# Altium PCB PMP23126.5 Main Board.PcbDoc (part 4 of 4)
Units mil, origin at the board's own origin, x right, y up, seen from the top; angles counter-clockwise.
Board outline 7480.32 x 4667 mil, 6 copper layers (Top Layer, Signal Layer 1, Signal Layer 2, Signal Layer 3, Signal Layer 4, Bottom Layer), stack 65.8 mil thick; 166 components, 83 nets, 633 pads, 4418 vias.
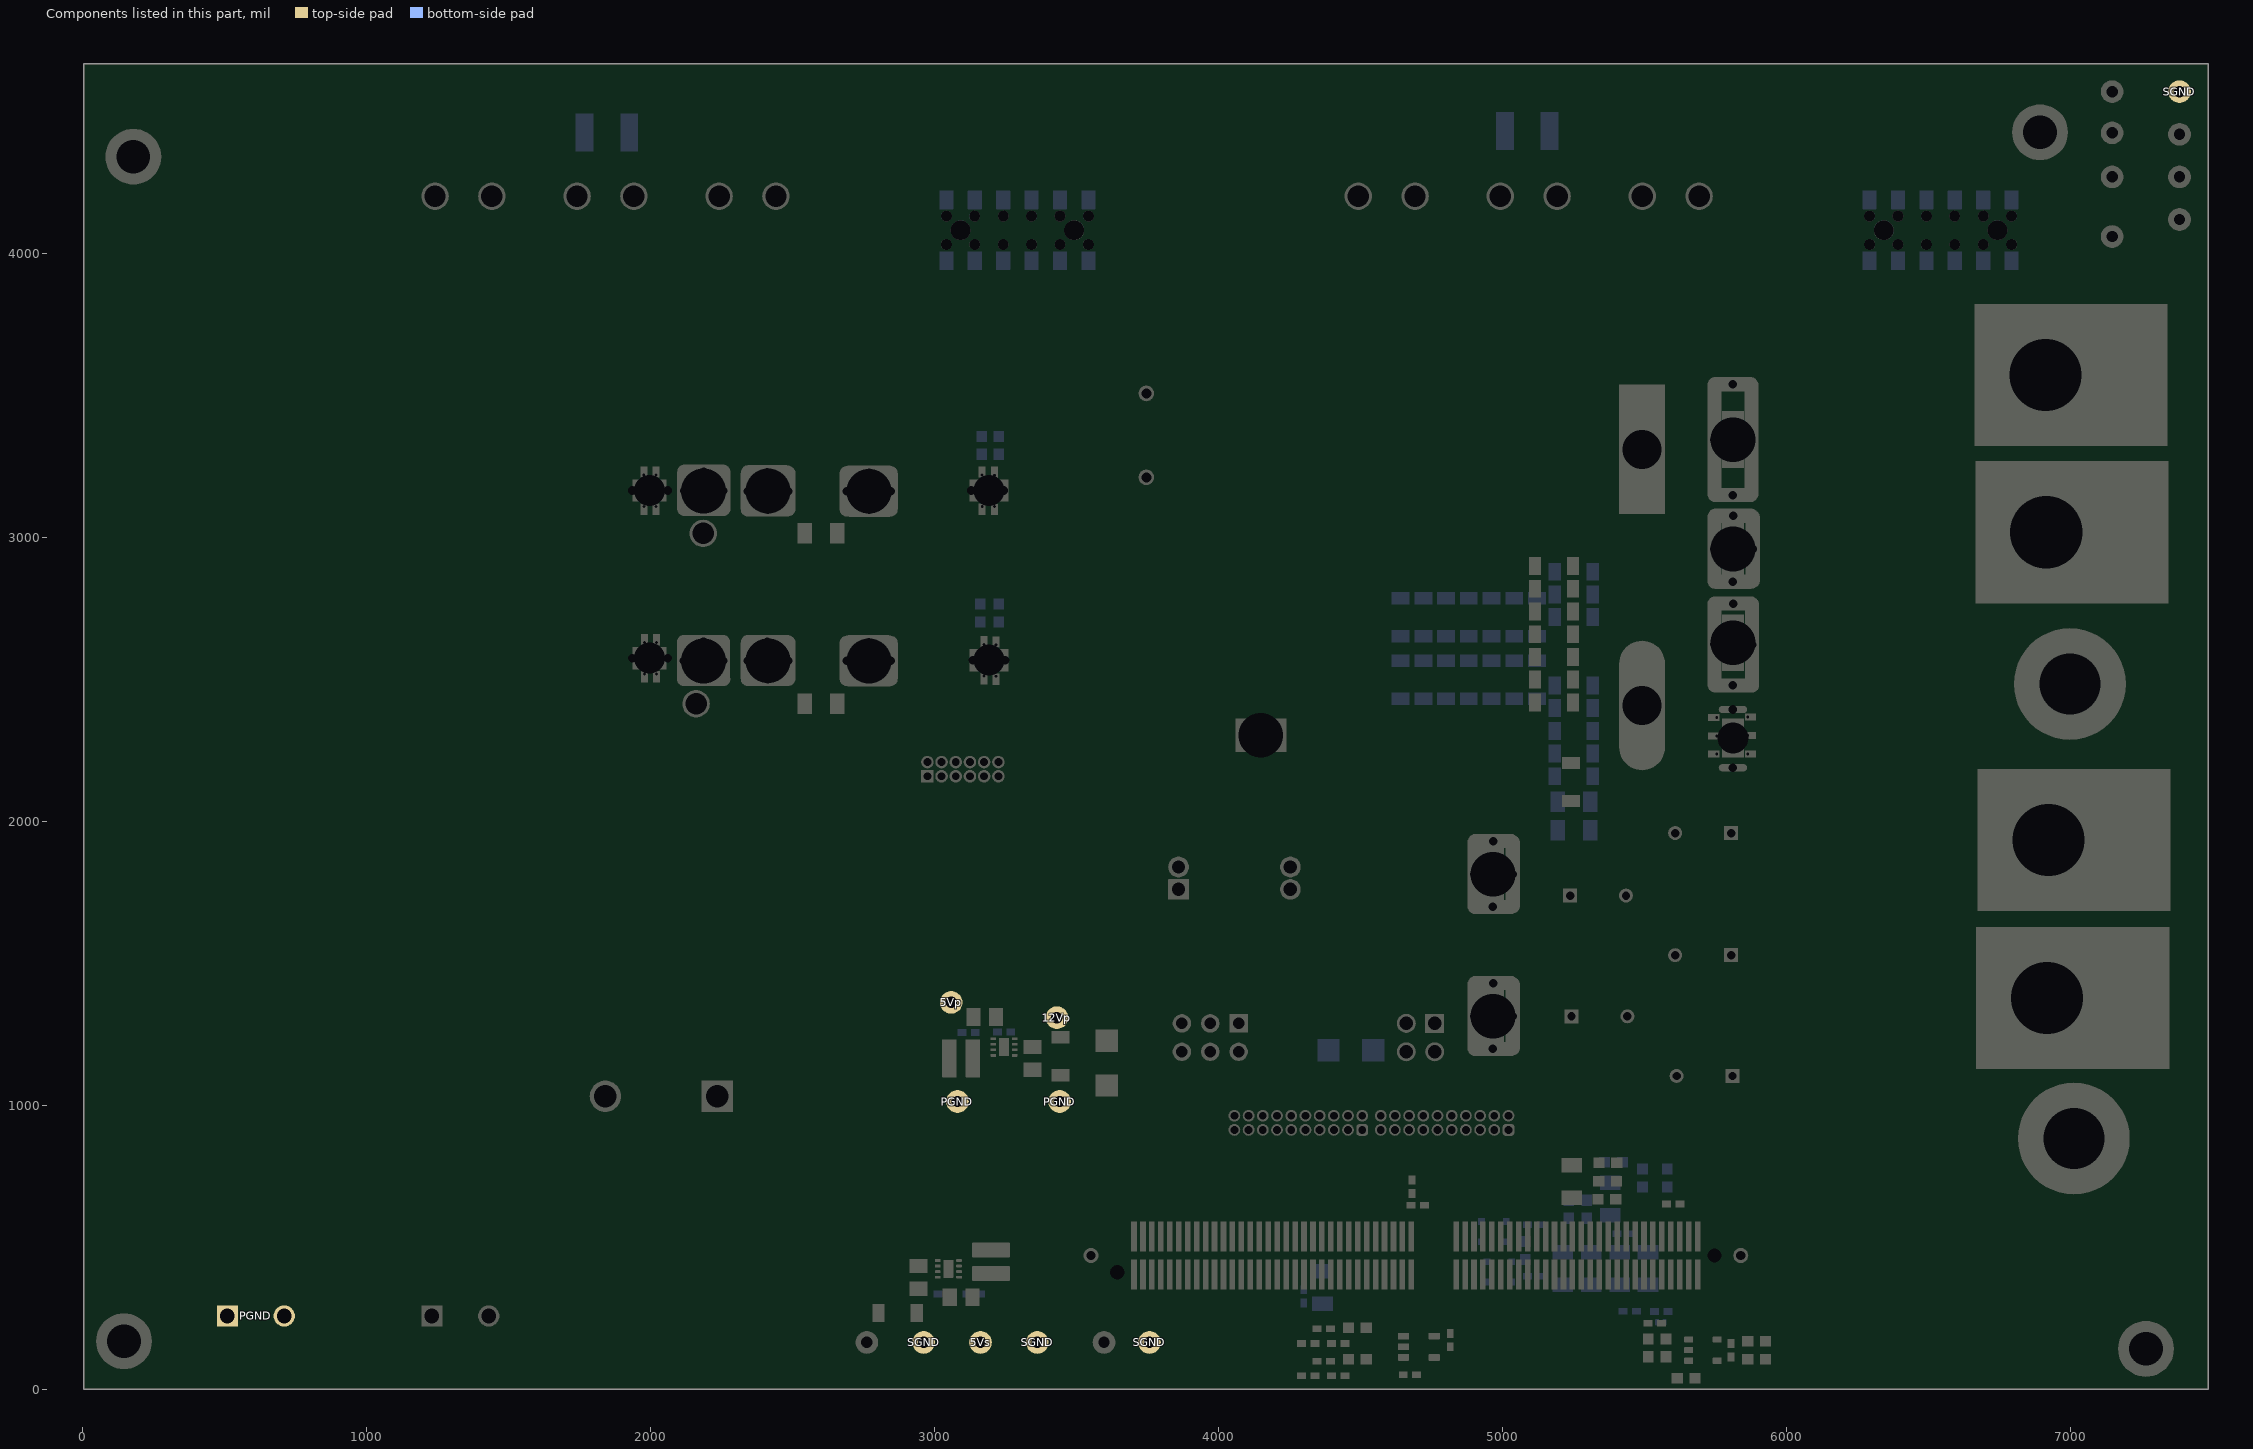
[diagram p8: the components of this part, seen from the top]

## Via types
v1: diameter 24, hole 8, Top Layer to Bottom Layer, 3810 vias
v2: diameter 32, hole 16, Top Layer to Bottom Layer, 232 vias
v3: diameter 24, hole 8, Top Layer to Bottom Layer, tented top, 210 vias
v4: diameter 20, hole 10, Top Layer to Bottom Layer, 76 vias
v5: diameter 20, hole 10, Top Layer to Bottom Layer, tented top, 57 vias
v6: diameter 24, hole 8, Top Layer to Bottom Layer, tented both sides, 29 vias
v7: diameter 19.68, hole 7.87, Top Layer to Bottom Layer, 4 vias

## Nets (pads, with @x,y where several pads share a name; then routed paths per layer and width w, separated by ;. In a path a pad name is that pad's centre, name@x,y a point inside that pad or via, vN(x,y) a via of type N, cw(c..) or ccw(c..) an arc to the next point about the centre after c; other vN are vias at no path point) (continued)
pads on no net: CT100.2 CT100.4 J101. J101.7 J101.9 J105. J105.9 J200.1 J200.2 J200.3 J200.4 J200.5 J200.6 J200.8 J200.11 J200.18 J200.21 J200.25 J200.26 J200.27 J200.28 J200.30 J200.31 J200.32 J200.33 J200.36 J200.37 J200.39 J200.40 J200.41 J200.42 J200.43 J200.44 J200.45 J200.48 J200.60 J200.66 J200.67 J200.69 J200.70 J200.71 J200.72 J200.73 J200.75 J200.77 J200.79 J200.80 J200.81 J200.82 J200.85 J200.86 J200.87 J200.88 J200.89 J200.90 J200.91 J200.92 J200.93 J200.94 J200.95 J200.96 J200.99 J200.100 J200.101 J200.102 J200.103 J200.104 J200.105 J200.106 J200.107 J200.108 J200.109 J200.110 J200.113 J200.114 J200.115 J200.116 J200.117 J200.118 J200.119 J200.120 J200.181 J200.182 J200.185 J200.186 J201.5 J201.6 J201.7 J201.8 J201.14 J201.16 J201.18 J202.2 J202.8 J202.10 J202.12 J202.14 J202.16 J202.18 J202.20 RT200.1S RT200.2S U100.8 U100.9@3244,1189 U100.9@3244,1224.43 U201.8 U201.9@3048.17,408.22 U201.9@3048.17,443.65 U203.4
copper on no net: | length 0.7
  Signal Layer 2 w25: 1978.04,2520.12 1978.56,2519.6
  other v4: 5735,2366.96 1977.91,2651 1975.91,3241

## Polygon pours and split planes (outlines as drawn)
SGND on Bottom Layer "BOTTOM_LAYER_SGND_P750" (solid, remove dead copper, pour order 750): 3050,2485 2870,2305 2870,2180 2870,1807 2991,1686 3831,1686 3995,1522 3995,1010 4440,1010 4440,2217 3300,2217 3300,3310 3185,3425 3075,3425 3050,3400
VBB on Bottom Layer "VBB" (solid, remove dead copper, pour order 83): 2890,3245 2870,3265 2650,3265 2630,3245 2630,2530 1980,1880 1980,950 1610,580 1230,580 1175,525 1175,140 1205,110 2120,110 2555,545 2555,2068.69 2805.35,2325 2890,2325
VSR on Bottom Layer "BOTTOM_LAYER_VSR_P076" (solid, remove dead copper, pour order 76): 5390,3550 5195,3355 4325,3355 4180,3210 4180,2835 4173.84,2403 4570,2403 4570,2887 4568,2889 4641,2962 5514,2962 5640,3088 5640,3550
12VB on Bottom Layer "BOTTOM_LAYER_12VB_P066" (solid, remove dead copper, pour order 66): 5720,3125 5925,3125 6030,3020 6030,2285 7355,2285 7355,3840 5995,3840 5720,3565
SGND on Bottom Layer "BOTTOM_LAYER_SGND_P060" (solid, remove dead copper, pour order 60): 4590,2740 4590,2885 4645,2940 5215,2940 5260,2895 5260,2685 5160,2685 5105,2740
SGND on Bottom Layer "BOTTOM_LAYER_SGND_P016" (solid, remove dead copper, pour order 16): 4600,2390 4590,2390 4580,2400 4580,2875 4600,2895 4615,2895 4615,2525 4630,2510 4635,2515 5210,2515 5210,1900 5250,1861 5426,1861 5804,2239 7435,2239 7438,663 6417,663 6083,997 5384,997 5285,898 4959,898 4959,1061 4869,1151 4689,1151 4491,1349 4491,2102 4600,2211
NetD200_1 on Bottom Layer "BOTTOM_LAYER_NETD200_1_P025" (solid, remove dead copper, pour order 25): 4994,608 4995,607 4995,499 5107,499 5106,500 5106,607
NetD202_2 on Bottom Layer "BOTTOM_LAYER_NETD202_2_P026" (solid, remove dead copper, pour order 26): 5013,484 5110,484 5110,351 5017,351 5014,354
VBB on Bottom Layer "BOTTOM_LAYER_VBB_P027" (solid, remove dead copper, pour order 27): 1124,4097 1573,4097 1573,4262 1571,4264 1652,4345 1652,4358 1824,4358 1828,4354 1846,4372 1846,4676 1366,4676 1122,4432 1122,4426
PGND on Bottom Layer "BOTTOM_LAYER_PGND_P028" (solid, remove dead copper, pour order 28): 1861,4676 1861,4339 1863,4341 2088,4341 2160,4269 2160,4125 2537,4125 2539,4123 2550,4134 2550,4452 2330,4672
VBB on Bottom Layer "BOTTOM_LAYER_VBB_P029" (solid, remove dead copper, pour order 29): 4384,4049 4388,4053 4388,4493 4565,4670 5077,4670 5077,4355 5080,4352 5071,4343 4871,4343 4811,4283 4812,4282 4812,4050
PGND on Bottom Layer "BOTTOM_LAYER_PGND_P030" (solid, remove dead copper, pour order 30): 5099,4668 5099,4352 5101,4354 5272,4354 5272,4353 5421,4204 5421,4062 5802,4062 5814,4050 5817,4053 5817,4503 5648,4672
PGND on Bottom Layer "BOTTOM_LAYER_PGND_P031" (solid, remove dead copper, pour order 31): 2740,918.42 2740,1263 2782,1305 2789,1298 3678,1298 3678,911.59
SGND on Bottom Layer "BOTTOM_LAYER_SGND_P037" (solid, remove dead copper, pour order 37): 2680,20 2695,5 6015,5 6031,20 6031,609 5801,839 4936,839 4842,745 3049,745 2680,376
SGND on Bottom Layer "BOTTOM_LAYER_SGND_P044" (solid, remove dead copper, pour order 44): 4450,2219 4450,696 5100,696 5100,2219
SGND on Bottom Layer "BOTTOM_LAYER_SGND_P049" (solid, remove dead copper, pour order 49): 4973,883 4921,831 4608,831 4455,984 4304,984 4304,858 4371,791 4369,789 4369,679 4984,679 4991,686
SWNODE2_1 on Bottom Layer "BOTTOM_LAYER_SWNODE2_1_P022" (solid, remove dead copper, pour order 22): 5029,3735 4205.59,3735 4085.59,3616 2361,3616 2290,3545 2085,3545 2085,3615 2370,3900 3947.81,3900 4022.81,3980 4875,3980 4928,4033 4928,4302 5291,4302 5297,4296 5297,4003
SWNODE1_1 on Bottom Layer "BOTTOM_LAYER_SWNODE1_1_P023" (solid, remove dead copper, pour order 23): 1855,2428 1855,2250 1335,2250 1157,2428 1157,3642 1448,3933 1667,4152 1667,4292 2033,4292 2040,4285 2037,4282 2037,4036 1515,3514 1517,3512 1517,2428
SWNODE1 on Bottom Layer "BOTTOM_LAYER_SWNODE1_P067" (solid, remove dead copper, pour order 67): 1875,2430 1875,2245 2190,2245 2285,2340 2285,2685 2090,2685 2080,2675 2080,2475 2035,2430
SWNODE2 on Bottom Layer "BOTTOM_LAYER_SWNODE2_P068" (solid, remove dead copper, pour order 68): 2290,3020 2235,2965 2140,2965 2085,3020 2085,3540 2290,3540
Iout_SNS on Bottom Layer "Iout_SNS" (solid, remove dead copper, pour order 1): 4615,2710 4625,2720 5110,2720 5150,2680 5210,2680 5270,2740 5270,2895 5315,2940 5595,2940 5725,2810 5885,2810 5900,2795 5910,2785 5910,2435 5890,2415 5725,2415 5695,2385 5695,2205 5865,2035 5865,1085 5840,1060 5705,1060 5475,1290 5475,1330 5160,1645 4885,1645 4865,1665 4865,1945 4880,1960 5135,1960 5170,1925 5210,1925 5230,1945 5230,2495 5200,2525 4640,2525 4615,2550
SGND on Top Layer "TOP_LAYER_SGND_P054" (solid, remove dead copper, pour order 54): 4460,1320 4675,1105 4675,1055 4460,1055 4460,1045 4310,1045 4260,1095 4260,1460 4035,1685 3045,1685 3040,1680 2890,1830 2890,2295 3065,2470 3065,3310 3300,3310 3300,2280 3295,2280 3359.29,2220 3745,2220 4460,1505
PGND on Top Layer "PGND" (solid, remove dead copper, pour order 88): 2005,3115 2000,3110 2000,3075 1995,3070 1840,3070 1815,3045 1815,2430 1840,2405 2015,2405 2040,2430 2040,3105 2030,3115
SWNODE1 on Top Layer "SWNODE1" (solid, remove dead copper, pour order 87): 2115,2660 2115,2385 2140,2360 2180,2360 2280,2460 2280,2645 2265,2660
SWNODE2 on Top Layer "SWNODE2" (solid, remove dead copper, pour order 86): 2125,3260 2125,2995 2155,2965 2215,2965 2280,3030 2280,3240 2260,3260
SGND on Top Layer "TOP_LAYER_SGND_P020" (solid, remove dead copper, pour order 20): 5770,905 5320,905 5190,1035 5115,1035 5115,2140 5525,2140 5638.45,2253.45 7364,2240.53 7364,669 6006,669
SGND on Top Layer "TOP_LAYER_SGND_P053" (solid, remove dead copper, pour order 53): 5205,2140 5205,1839 5445,1839 5444,1840 5444,2140
12VB on Top Layer "TOP_LAYER_12VB_P061" (solid, remove dead copper, pour order 61): 5720,3125 5925,3125 6030,3020 6030,2285 7355,2285 7355,3840 5995,3840 5720,3565
Iout_SNS on Top Layer "TOP_LAYER_IOUT_SNS_P059" (solid, remove dead copper, pour order 59): 5725,2810 5595,2940 5230,2940 5210,2920 5210,2195 5245,2160 5510,2160 5700,2350 5700,2400 5735,2435 5915,2435 5915,2805 5910,2810
VSR on Top Layer "TOP_LAYER_VSR_P015" (solid, remove dead copper, pour order 15): 4180,2825 4180,3293 4427,3540 5640,3540 5640,3078 5514,2952 4645,2952 4570,2877 4570,2393 4173.84,2393
SGND on Top Layer "TOP_LAYER_SGND_P021" (solid, remove dead copper, pour order 21): 4855,1145 4855,1100 4870.68,1084.32 4931,1086 4972,1045 5386.06,1045 5460,1120 5460,1850 5370,1940 5300,1940 5280,1960 5280,2130 5270,2140 5230,2140 5190,2180 5190,2925 5170,2945 4655,2945 4585,2875 4585,2405 4600,2390 5030,2390 5040,2380 5040,2220 5030,2210 4600,2210 4502.5,2112.5 4502.5,2107.5 4496,2101 4496,1340 4684,1152 4848,1152
PGND on Top Layer "TOP_LAYER_PGND_P038" (solid, remove dead copper, pour order 38): 1930,1325 1930,1130 1935,1125 2485,1125 2765,845 2765,840 2800,805 3690,805 3690,995 3665,1020 3565,1020 3555,1030 3555,1160 3540,1175 3315,1175 3305,1185 3305,1300 3300,1305 3255,1305 3220,1270 3220,1165 3140,1085 3030,1085 3020,1095 3020,1250 2945,1325
SGND on Top Layer "TOP_LAYER_SGND_P040" (solid, remove dead copper, pour order 40): 4968,878 4966,876 4553,876 4450,979 4299,979 4299,853 4366,786 4364,784 4364,674 4979,674 4986,681
SGND on Top Layer "TOP_LAYER_SGND_P052" (solid, remove dead copper, pour order 52): 6550,3926 6549,3925 6245,3925 6200,3970 6200,4185 6035,4348 3820,4348 3655,4185 3655,4000 3610,3955 2970,3955 2870,4055 2870,4595 2945,4670 3312.99,4670 3315,4667.99 7479,4661 7476,4658 7476,3926
VBB on Top Layer "VBB" (solid, remove dead copper, pour order 77): 2650,3260 2635,3245 2635,2990 2650,2975 2870,2975 2880,2985 2880,3240 2860,3260
VBB on Top Layer "VBB" (solid, remove dead copper, pour order 78): 2650,2660 2635,2645 2635,2390 2650,2375 2870,2375 2880,2385 2880,2640 2860,2660
PGND on Top Layer "TOP_LAYER_PGND_P079" (solid, remove dead copper, pour order 79): 5800,4035 5560,3795 4335,3795 4140,3600 2890,3600 2825,3535 2825,3380 2800,3355 2650,3355 2565,3270 2565,2085 1977.5,1497.5 1977.5,972.5 1585,580 950,580 840,470 845,465 845,100 375,95 375,695 910,1230 1165,1230 1855,1920 2315,2380 2315,3665 2155,3825 2155,4255 2185,4285 2505,4285 2535,4255 2535,4025 2660,3900 3760,3900 3870,4010 5395,4010 5430,4045 5430,4250 5465,4285 5765,4285 5800,4250
5Vp on Top Layer "5Vp" (solid, remove dead copper, pour order 5): 3013,1267 3025,1255 3025,1100 3030,1095 3085,1095 3095,1105 3095,1230 3110,1245 3145,1245 3165,1265 3164.5,1275.5 3166,1277 3166,1382 3135,1413 3014,1413 3013,1412
12Vp on Top Layer "12Vp" (solid, remove dead copper, pour order 4): 3325,1180 3315,1190 3315,1250 3450,1385 3535,1385 3685,1235 3685,1215 3650,1180
5Vs on Top Layer "5Vs" (solid, remove dead copper, pour order 0): 3125,440 3115,430 3115,145 3135,125 3255,125 3270,140 3270,430 3260,440
SGND on Top Layer "TOP_LAYER_SGND_P740" (solid, remove dead copper, pour order 740): 6025,630 6080,575 6080,70 6015,5 2695,5 2680,20 2680,376 3049,745 3435,745 3795,1105 5125,1105 5170,1060 5170,1025 5305,890 5765,890
SGND on Signal Layer 1 "SIGNAL_LAYER_1_SGND_P752" (solid, remove dead copper, pour order 752): 6550,3926 6549,3925 6245,3925 6200,3970 6200,4185 6035,4348 3820,4348 3655,4185 3655,4000 3610,3955 2970,3955 2870,4055 2870,4595 2945,4670 3312.99,4670 3315,4667.99 7479,4661 7476,4658 7476,3926
VBB on Signal Layer 1 "VBB" (solid, remove dead copper, pour order 82): 4386,4195 4451,4260 4745,4260 4811,4195 4811,3739 4669,3597 2957,3597 2890,3530 2890,2325 2805.35,2325 2555,2068.69 2555,545 2120,110 1205,110 1175,140 1175,525 1230,580 1610,580 1980,950 1980,1880 2550,2450 2550,3250 2507.5,3292.5 2480,3320 1575,3320 1160,3735 1160,4260 1195,4298 1568,4298 1568,4060 1729,3899 4238,3899 4386,4047
SGND on Signal Layer 1 "SIGNAL_LAYER_1_SGND_P041" (solid, remove dead copper, pour order 41): 2870,3535 2870,1807 2991,1686 3831,1686 3995,1522 3995,1010 4440,1010 4440,2217 3300,2217 3300,3535
12VB on Signal Layer 1 "SIGNAL_LAYER_1_12VB_P062" (solid, remove dead copper, pour order 62): 5720,3125 5925,3125 6030,3020 6030,2285 7355,2285 7355,3840 5995,3840 5720,3565
VSR on Signal Layer 1 "SIGNAL_LAYER_1_VSR_P055" (solid, remove dead copper, pour order 55): 4226,3349 4226,3346 4160,3280 4160,2445 4175,2430 4570,2430 4570,2887 4568,2889 4641,2962 5514,2962 5640,3088 5640,3550 4427,3550
SGND on Signal Layer 1 "SIGNAL_LAYER_1_SGND_P019" (solid, remove dead copper, pour order 19): 4450,1110 4870,1110 5070,910 5755,910 5865,800 6317,800 6448,669 7366,669 7366,2240.52 7365,2240.52 7350.53,2255 4450,2255
Iout_SNS on Signal Layer 1 "Iout_SNS" (solid, remove dead copper, pour order 3): 5910,2785 5900,2795 4680,2795 4645,2760 4645,2545 4680,2510 5020,2510 5045,2485 5045,2195 4865,2015 4865,1665 4885,1645 5370,1645 5395,1670 5395,1805 5695,2105 5695,2385 5725,2415 5890,2415 5910,2435
SGND on Signal Layer 1 "SGND" (solid, remove dead copper, pour order 93): 4580,2425 4170,2425 4150,2445 4150,3025 3915,3260 3725,3260 3710,3245 3710,3190 3725,3175 3885,3175 4055,3005 4055,2460 4125,2390 5030,2390 5080,2440 5080,2915 5055,2940 4645,2940 4580,2875
SGND on Signal Layer 1 "SIGNAL_LAYER_1_SGND_P742" (solid, remove dead copper, pour order 742): 2680,20 2695,5 6015,5 6031,20 6031,609 5750,890 4065,890 3920,745 3049,745 2680,376
SGND on Signal Layer 2 "SIGNAL_LAYER_2_SGND_P748" (solid, remove dead copper, pour order 748): 2785,3535 2785,1892 3027,1650 3867,1650 3995,1522 3995,1010 4440,1010 4440,2217 3300,2217 3300,3535
PGND on Signal Layer 2 "PGND" (solid, remove dead copper, pour order 90): 2005,3115 2000,3110 2000,3075 1995,3070 1840,3070 1815,3045 1815,2430 1840,2405 2015,2405 2040,2430 2040,3105 2030,3115
PGND on Signal Layer 2 "PGND" (solid, remove dead copper, pour order 81): 1977.5,1497.5 1977.5,972.5 1585,580 950,580 840,470 845,465 845,100 375,95 375,695 910,1230 1165,1230 1855,1920 2315,2380 2315,3665 2155,3825 2155,4255 2185,4285 2505,4285 2535,4255 2535,4025 2660,3900 5285,3900 5430,4045 5430,4250 5465,4285 5765,4285 5800,4250 5800,3870 5530,3600 2890,3600 2825,3535 2825,3380 2800,3355 2650,3355 2565,3270 2565,2085
SGND on Signal Layer 2 "SIGNAL_LAYER_2_SGND_P042" (solid, remove dead copper, pour order 42): 4450,2217 4450,1249 4794,905 5390,905 5415,905 5450,870 5790,870 5855,805 6280,805 6280,870 6150,1000 6150,2135 6040,2245 5935,2245 5875,2185 5875,1380 5430,1380 5390,1420 5390,2217
12VB on Signal Layer 2 "SIGNAL_LAYER_2_12VB_P063" (solid, remove dead copper, pour order 63): 5720,3125 5925,3125 6030,3020 6030,2285 7355,2285 7355,3840 5995,3840 5720,3565
VSR on Signal Layer 2 "SIGNAL_LAYER_2_VSR_P056" (solid, remove dead copper, pour order 56): 4175,2395 4160,2410 4160,3280 4180,3300 4180,3303 4427,3550 5640,3550 5640,3088 5514,2962 4641,2962 4568,2889 4570,2887 4570,2395
SGND on Signal Layer 2 "SIGNAL_LAYER_2_SGND_P018" (solid, remove dead copper, pour order 18): 7435,2210 7400,2245 5960,2245 5960,1116 6408,668 7435,668
SGND on Signal Layer 2 "SIGNAL_LAYER_2_SGND_P046" (solid, remove dead copper, pour order 46): 4969,885 4967,883 4554,883 4451,986 4300,986 4300,860 4367,793 4365,791 4365,681 4980,681 4987,688
PGND on Signal Layer 2 "PGND" (solid, remove dead copper, pour order 80): 2805,1415 2745,1355 2745,860 2800,805 3690,805 3690,1090 3700,1100 4010,1100 4025,1115 4025,1375 3985,1415
Iout_SNS on Signal Layer 2 "Iout_SNS" (solid, remove dead copper, pour order 2): 5695,2205 5865,2035 5865,1085 5840,1060 5705,1060 5475,1290 5475,1330 5160,1645 4885,1645 4865,1665 4865,2015 5045,2195 5045,2485 5020,2510 4680,2510 4645,2545 4645,2760 4680,2795 5900,2795 5910,2785 5910,2435 5890,2415 5725,2415 5695,2385
SGND on Signal Layer 2 "SGND" (solid, remove dead copper, pour order 94): 5055,2940 5080,2915 5080,2440 5035,2395 4585,2395 4580,2400 4580,2875 4645,2940
SGND on Signal Layer 2 "SIGNAL_LAYER_2_SGND_P744" (solid, remove dead copper, pour order 744): 2680,20 2695,5 6015,5 6031,20 6031,609 5801,839 4936,839 4842,745 3049,745 2680,376
PGND on Signal Layer 3 "PGND" (solid, remove dead copper, pour order 85): 2005,2210 2005,2510 2010,2515 2050,2515 2060,2505 2060,2335 2840,1555 3300,1555 3455,1400 3735,1400 4000,1400 4025,1375 4025,1115 4010,1100 3700,1100 3685,1085 3685,815 3665,795 2810,795 2765,840 2765,1240 2795,1270 2840,1270 2840,1375
PGND on Signal Layer 3 "PGND" (solid, remove dead copper, pour order 84): 2565,2515 2520,2470 1915,2470 1880,2435 1880,1100 1910,1070 1912.5,907.5 1585,580 950,580 840,470 845,465 845,100 375,95 375,695 910,1230 1165,1230 1535,1600 1535,3635 2185,4285 2505,4285 2535,4255 2535,4025 2660,3900 5285,3900 5430,4045 5430,4250 5465,4285 5765,4285 5800,4250 5800,3870 5530,3600 2890,3600 2825,3535 2825,3380 2800,3355 2650,3355 2565,3270
PGND on Signal Layer 3 "PGND" (solid, remove dead copper, pour order 89): 2005,3115 2000,3110 2000,3075 1995,3070 1840,3070 1815,3045 1815,2430 1840,2405 2015,2405 2040,2430 2040,3105 2030,3115
Iout_SNS on Signal Layer 3 "SIGNAL_LAYER_3_IOUT_SNS_P070" (solid, remove dead copper, pour order 70): 5400,2235 5400,2230 5485,2145 5490,2145 5545,2145 5630,2230 5630,2355 5710,2435 5920,2435 5920,2810 5565,2810 5400,2645
12VB on Signal Layer 3 "SIGNAL_LAYER_3_12VB_P064" (solid, remove dead copper, pour order 64): 5720,3125 5925,3125 6030,3020 6030,2285 7355,2285 7355,3840 5995,3840 5720,3565
VSR on Signal Layer 3 "SIGNAL_LAYER_3_VSR_P057" (solid, remove dead copper, pour order 57): 4160,3273 4160,2405 4175,2393 4570,2393 4570,2877 4568,2879 4641,2952 5514,2952 5640,3078 5640,3540 4427,3540
SGND on Signal Layer 3 "SIGNAL_LAYER_3_SGND_P017" (solid, remove dead copper, pour order 17): 5390,2213 5390,2865 5315,2940 4645,2940 4585,2880 4585,2405 4600,2390 4610,2390 4610,2225 4600,2213 4599,2213 4500,2114 4500,1235 4645,1090 4840,1090 4958,972 4958,864 5320,864 5806,864 6005,665 7352.46,665 7349.46,2241 6036,2241 5970,2175 5425,2175
SGND on Signal Layer 3 "SIGNAL_LAYER_3_SGND_P746" (solid, remove dead copper, pour order 746): 2680,20 2695,5 6015,5 6031,20 6031,609 5801,839 4936,839 4842,745 3049,745 2680,376
SGND on Signal Layer 4 "SIGNAL_LAYER_4_SGND_P754" (solid, remove dead copper, pour order 754): 6550,3926 6549,3925 6245,3925 6200,3970 6200,4185 6035,4348 3820,4348 3655,4185 3655,4000 3610,3955 2970,3955 2870,4055 2870,4595 2945,4670 3312.99,4670 3315,4667.99 7479,4661 7476,4658 7476,3926
VBB on Signal Layer 4 "SIGNAL_LAYER_4_VBB_P024" (solid, remove dead copper, pour order 24): 2550,2450 1980,1880 1980,950 1610,580 1230,580 1175,525 1175,140 1205,110 2120,110 2555,545 2555,2068.69 2805.35,2325 2890,2325 2890,3530 2957,3597 4669,3597 4811,3739 4811,4279 4798,4266 4386,4266 4386,4047 4238,3899 1729,3899 1568,4060 1568,4298 1195,4298 1160,4260 1160,3735 1575,3320 2480,3320 2507.5,3292.5 2550,3250
SGND on Signal Layer 4 "SIGNAL_LAYER_4_SGND_P071" (solid, remove dead copper, pour order 71): 5525,2065 5525,2100 5645,2220 5645,2345 5725,2425 5965,2425 6050,2340 6050,2055
12VB on Signal Layer 4 "SIGNAL_LAYER_4_12VB_P065" (solid, remove dead copper, pour order 65): 5720,3125 5925,3125 6030,3020 6030,2285 7355,2285 7355,3840 5995,3840 5720,3565
VSR on Signal Layer 4 "SIGNAL_LAYER_4_VSR_P058" (solid, remove dead copper, pour order 58): 4180,2835 4180,3303 4427,3550 5640,3550 5640,3088 5514,2962 4641,2962 4568,2889 4570,2887 4570,2403 4173.84,2403
SGND on Signal Layer 4 "SIGNAL_LAYER_4_SGND_P043" (solid, remove dead copper, pour order 43): 2740,3301.07 2740,1939 2991,1688 3932,1688 4138,1482 4138,1040 4435,1040 4435,1922 4138,2219 3295,2219 3295,3308.22
SGND on Signal Layer 4 "SGND" (solid, remove dead copper, pour order 91): 5390,2213 5390,2865 5315,2940 4645,2940 4585,2880 4585,2405 4600,2390 4610,2390 4610,2225 4600,2213 4599,2213 4500,2114 4500,1235 4645,1090 4840,1090 5020,910 5765,910 6010,665 7352.46,665 7349.46,2241 6036,2241 5970,2175 5425,2175
Iout_SNS on Signal Layer 4 "SIGNAL_LAYER_4_IOUT_SNS_P092" (solid, remove dead copper, pour order 92): 5400,2235 5400,2230 5485,2145 5490,2145 5545,2145 5630,2230 5630,2355 5710,2435 5920,2435 5920,2810 5565,2810 5400,2645
SGND on Signal Layer 4 "SIGNAL_LAYER_4_SGND_P738" (solid, remove dead copper, pour order 738): 3730,770 3730,1040 3740,1050 5060,1050 5215,895 5745,895 6031,609 6031,20 6015,5 2695,5 2680,20 2680,376 3049,745 3705,745
no net on Top Solder "NONET_L-01_P-001" (solid, pour order 12): 4495,2020 4495,1520 4605,1410 4785,1410 4845,1350 4845,1185 4900,1130 5075,1130 5110,1165 5110,1515 5020,1605 4895,1605 4845,1655 4845,1945 4890,1990 5085,1990 5085,2015 5080,2020
no net on Top Solder "TOP_LAYER_NONET_P-001" (solid, pour order 13): 7355,2250 6500,2250 6385,2135 5875,2135 5875,1125 5990,1125 6450,665 7365,665
no net on Top Solder "TOP_LAYER_NONET_P-001" (solid, pour order 14): 4600,2210 4495,2105 4495,1985 5085,1985 5085,2210
no net on Top Solder "BOTTOM_LAYER_NONET_P665" (solid, pour order 72): 5910,3125 5925,3125 6030,3020 6030,2285 7355,2285 7355,3840 5995,3840 5910,3755
no net on Bottom Solder "TOP_LAYER_NONET_P-001" (solid, pour order 6): 4600,2215 4495,2110 4495,1990 5085,1990 5085,2215
no net on Bottom Solder "NONET_L-01_P-001" (solid, pour order 7): 4495,2025 4495,1525 4605,1415 4785,1415 4845,1355 4845,1190 4900,1135 5075,1135 5110,1170 5110,1520 5020,1610 4895,1610 4845,1660 4845,1950 4890,1995 5085,1995 5085,2020 5080,2025
no net on Bottom Solder "TOP_LAYER_NONET_P-001" (solid, pour order 8): 7355,2255 6500,2255 6385,2140 5875,2140 5875,1130 5990,1130 6450,670 7365,670
no net on Bottom Solder "BOTTOM_LAYER_NONET_P665" (solid, pour order 9): 5905,3125 5920,3125 6025,3020 6025,2285 7350,2285 7350,3840 5990,3840 5905,3755
no net on Bottom Solder "NONET_L-01_P-001" (solid, pour order 10): 1807,2426.5 1807,2245 1955,2245 1955,2425.5
no net on Bottom Solder "NONET_L-01_P-001" (solid, pour order 11): 2084.5,3470 2295.5,3470 2295.5,3618 2085.5,3618

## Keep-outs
Keep-Out Layer:
  text ".Layer_Name" at 577,-858.49 h60

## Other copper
Top Layer:
  text ".Layer_Name" at 527.56,-113.19 h60
Signal Layer 4:
  pour cut-out: 5691,702 5731,702 5731,662 5691,662
Bottom Layer:
  region net VSR: 4177,2832.25 4177,2394.25 4568.33,2394.25 4568.33,2403.25 4568.33,2832.25
  text ".Layer_Name" at 577,-858.49 h60

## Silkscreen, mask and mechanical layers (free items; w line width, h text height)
Top Overlay:
  rectangle: 200,490 1110,690
  lines w7.01: 1902.73,3543.31 5918.48,3543.31 5918.48,866.14 3791.5,866.14 ; 4835,1730 3810,1730 3810,1139.45 4835,1140 4835,1730.55 ; 3270,1944.41 3270,2220 5270,2220 5270,1944.41 3270,1944.41
  lines w7.87: 1866.49,1816.21 1866.49,3391.02 ; 1866.67,1815.81 764.31,1815.81 764.31,3390.61 1866.67,3390.61
  lines w10: 1902.73,2047 1902.73,3543 ; 1902.73,2047.24 3794,2047.24 ; 1966,2671.17 2876.91,2671.17 ; 1971,2946.76 2908,2946.76 ; 1980,3267.72 2892,3267.72 ; 2892,3325 2894,3327 ; 3795,866.14 3795,2047.24 ; 6027.22,135.86 6129.58,135.86 6176.83,183.1 6176.83,257.91 ; 6140,260 6125,260 ; 7065,4280 7065,4315 7110,4360 ; 7120,4170 7130,4170 7145,4185 7145,4200 ; 6125,260 6075,310 6065,320 6065,490 6095,520 6450,520 6500,470 6500,295 6465,260 6125,260
  text "Reserved for heatsink" at 2010,3395 h72.83
  text "No component or HV trace." at 2010,3330 h72.83
  text "Place holder for fan" at 983.49,3262.21 h90
  text "Reserved for heatsink" at 2025,2865 h72.83
  text "No component or HV trace." at 2025,2800 h72.83
  text "Reserve for SR HS" at 3470,2090 h72.83
  text "Reserve for AUX Supply" at 3830,1610 h72.83
  text "PMP23126RevA" at 205,775 h150
  text "-" at 310,90 h120
  text "+" at 1560,90 h120
  text ".Layer_Name" at 577,-858.49 h60
Bottom Overlay:
  lines w10: 5111,317 5111,377 ; 5431,662 5441,662 5456,647 5476,627 5506,627
  text ".Layer_Name" at 577,-858.49 h60
Top Paste:
  text ".Layer_Name" at 577,-858.49 h60
Bottom Paste:
  text ".Layer_Name" at 577,-858.49 h60
Top Solder:
  text ".Layer_Name" at 577,-858.49 h60
  text ".Layer_Name" at 577,-858.49 h60
Bottom Solder:
  region: 4175,2835 4175,2397 4569,2397 4569,2406 4569,2835
  text ".Layer_Name" at 577,-858.49 h60
Drill Guide:
  text ".Layer_Name" at 577,-858.49 h60
M1 Board Outline:
  lines w7: 3.6,4669 7483.91,4669 7483.91,2 3.6,2 5,4669
  text ".Layer_Name" at 577,-858.49 h60
M2 Board Dimensions:
  rectangle: 125,-400 500,-275
  rectangle: 0,-275 125,-150
  lines w7: 0,-275 1000,-275 ; 125,-400 125,-150 ; 250,-400 250,-150 ; 500,-400 500,-150 ; 750,-400 750,-150 ; 0,-400 0,-150 1000,-150 1000,-400 0,-400
  text ".Layer_Name" at 577,-858.49 h60
M3 3D STEP Top:
  text ".Layer_Name" at 577,-858.49 h60
M4 3D STEP Bottom:
  text ".Layer_Name" at 577,-858.49 h60
M5 Assembly Top:
  lines w10: -292,-930.17 6308,-930.17 ; -292,-726.83 6310,-726.83 ; -292,-523.5 -292,-1133.5 3713,-1133.5 6310,-1133.5 6310,-523.5 -291.5,-523.5 -291.5,-1133.5 1284,-1133.5 ; 2173,-1133.5 2173,-523.5 ; 3440,-726.83 3440,-523.5 ; 4280,-726.83 4280,-523.5 ; 4902,-1140 4902,-937.17
  text "COMPONENTS MARKED 'DNP' SHOULD NOT BE POPULATED." at 1153.5,-318.5 h60
  text "ASSEMBLY VARIANT:" at 1153,-434 h60
  text ".VariantName" at 2189,-434 h60
  text "PCB VIEWED FROM TOP SIDE" at -228.5,-655.67 h60
  text "BOARD #:" at 2248,-655.67 h60
  text ".PRJ_Number" at 2793.5,-655.67 h60
  text "REV:" at 3638,-655.67 h60
  text ".PCB_Rev" at 3929.5,-655.67 h60
  text "SVN REV:" at 4476,-655.67 h60
  text ".VersionControl_RevNumber" at 4982,-655.67 h60
  text "TID #:" at 2248,-859 h60
  text ".TID" at 2793.5,-859 h60
  text "PLOT NAME =" at -228.5,-1064.34 h60
  text ".plot_File_Name" at 577,-1064.34 h60
  text "GENERATED    :" at 2250,-1064.34 h60
  text ".Print_Date" at 3119.5,-1064.34 h60
  text ".Print_Time" at 3848.5,-1064.34 h60
  text "TEXAS INSTRUMENTS" at 5113,-1064.34 h60
M6 Assembly Bottom:
  lines w10: -292.5,-727.33 6309.5,-727.33 ; -290.5,-930.67 6309.5,-930.67 ; 1115.5,-1140.5 1115.5,-937.67 ; 1737.5,-727.33 1737.5,-524 ; 2577.5,-727.33 2577.5,-524 ; 3844.5,-1134 3844.5,-524 ; 4733.5,-1134 6309,-1134 6309,-524 -292.5,-524 -292.5,-1134 2304.5,-1134 6309.5,-1134 6309.5,-524
  text "COMPONENTS MARKED 'DNP' SHOULD NOT BE POPULATED." at 6853.97,-314.06 h60
  text ".VariantName" at 5058,-434 h60
  text "ASSEMBLY VARIANT:" at 6097,-434 h60
  text ".VersionControl_RevNumber" at 1035.5,-656.17 h60
  text "SVN REV:" at 1541.5,-656.17 h60
  text ".PCB_Rev" at 2088,-656.17 h60
  text "REV:" at 2379.5,-656.17 h60
  text ".PRJ_Number" at 3224,-656.17 h60
  text "BOARD #:" at 3769.5,-656.17 h60
  text "PCB VIEWED FROM BOTTOM SIDE" at 6246,-656.17 h60
  text ".TID" at 3224,-859.5 h60
  text "TID #:" at 3769.5,-859.5 h60
  text "TEXAS INSTRUMENTS" at 904.5,-1064.84 h60
  text ".Print_Time" at 2169,-1064.84 h60
  text ".Print_Date" at 2898,-1064.84 h60
  text "GENERATED    :" at 3767.5,-1064.84 h60
  text ".plot_File_Name" at 5440.5,-1064.84 h60
  text "PLOT NAME =" at 6246,-1064.84 h60
M9 Title Sheet:
  drawing of 55 lines, arcs and shapes, not listed
  text "1" at 739.84,8036.5 h70
  text "2" at 3235.5,8036.5 h70
  text "3" at 5724.84,8036.5 h70
  text "4" at 8231.51,8036.5 h70
  text "5" at 10730.5,8036.5 h70
  text "6" at 13235.5,8036.5 h70
  text "A" at -416.5,6893.5 h70
  text "A" at 14383.5,6893.5 h70
  text "B" at 14383.5,4513.5 h70
  text "C" at 374.5,2140.5 h70
  text "C" at 14383.5,2138.5 h70
  text "PROJECT TITLE:" at 11343.5,277.5 h45
  text ".PRJ_Title" at 11393.5,144.17 h70
  text "DESIGNED FOR:" at 11343.5,-23.5 h45
  text ".PRJ_Customer" at 11393.5,-163.5 h70
  text "D" at -416.5,-231.5 h70
  text "D" at 14383.5,-231.5 h70
  text "FILE NAME:" at 11343.5,-323.5 h45
  text ".PCB_File_Name_No_Path" at 11393.5,-443.5 h70
  text "Texas Instruments (TI) and/or its licensors do not warrant the accuracy or completeness of this specification" at 6374,-605.34 h45
  text "ENGINEER:" at 11343.5,-613.5 h45
  text "LAYOUT BY:" at 12848.5,-613.5 h45
  text "or any information contained therein. TI and/or its licensors do not warrant that this design will meet" at 6329.01,-718 h45
  text ".PRJ_Engineer" at 11393.5,-768.49 h70
  text ".PCB_Layout" at 12899,-768.49 h70
  text "the specifications, will be suitable for your application or fit for any particular purpose, or will operate in" at 6329.01,-830.67 h45
  text ".Layer_Name" at 577,-858.49 h60
  text "ALTIUM DESIGNER VERSION:" at 12848.5,-923.5 h45
  text "an implementation. TI and/or its licensors do not warrant that the design is production worthy. You should" at 6329.01,-943.33 h45
  text "completely validate and test your design implementation to confirm the system functionality for your application." at 6374,-1056 h45
  text ".print_Scale" at 11393.5,-1056.83 h70
  text ".Application_BuildNumber" at 12899,-1056.83 h70
  text "1" at 739.84,-1263.5 h70
  text "2" at 3235.5,-1263.5 h70
  text "3" at 5724.84,-1263.5 h70
  text "4" at 8231.51,-1263.5 h70
  text "5" at 10730.5,-1263.5 h70
  text "6" at 13235.5,-1263.5 h70
M10 Fab Notes:
  drawing of 189 lines, arcs and shapes, not listed
  text "DESIGN INFORMATION" at 12382.02,6356.17 h60
  text "MIN. TRACK WIDTH:" at 11737.46,6224.05 h60
  text "8" at 12833.7,6224.05 h60
  text "MIL" at 12988.46,6224.05 h60
  text "MIN. CLEARANCE:" at 11737.46,6099.92 h60
  text "0.2" at 12773.7,6099.93 h60
  text "mm" at 12988.46,6099.92 h60
  text "MIN. VIA PAD SIZE:" at 11737.46,5975.8 h60
  text "20" at 12803.71,5975.8 h60
  text "MIL" at 12988.46,5975.8 h60
  text "0.05mm (2MIL)" at 12432.46,5845.9 h60
  text "MINIMUM ANNULAR RING" at 11408.23,5837.67 h60
  text "EXTERNAL" at 13140.46,5837.67 h60
  text "PER" at 11608.23,5727.55 h60
  text "IPC-D-275 CLASS 2 LEVEL C" at 11828.23,5727.54 h60
  text "MIL, HOLES" at 13316.46,5627.07 h60
  text "+/-" at 12924,5618.48 h60
  text "+/-" at 13778,5618.48 h60
  text "REGISTRATION TOLERANCES:" at 11408.23,5617.42 h60
  text "METAL" at 12608,5617.42 h60
  text "5" at 13184.2,5617.42 h60
  text "3" at 14017.2,5617.42 h60
  text "MIL" at 14133.46,5617.42 h60
  text "HOLE SIZE TOLERANCE (UNLESS OTHERWISE SPECIFIED):" at 11408.23,5519.1 h60
  text "+/-" at 13778,5516.23 h60
  text "3" at 14017.2,5515.17 h60
  text "MIL" at 14133.46,5515.17 h60
  text "MATERIAL:" at 11333.46,5377.52 h60
  text "FR-4 High Tg" at 12319.9,5249 h60
  text "X" at 12175.46,5241.01 h60
  text "FR-408" at 11754.46,5236.49 h60
  text "OTHER" at 13242.46,5236.49 h60
  text "62 MIL (1.6mm) +/-10%" at 12074.56,5093.46 h60
  text "X" at 11954.46,5091.01 h60
  text "THICKNESS:" at 11408.23,5085.24 h60
  text "OTHER" at 13359.46,5085.24 h60
  text "TOLERANCE:" at 11408.23,4946.92 h60
  text "X" at 12256.46,4946.92 h60
  text "ANSI IPC-6012 TYPE 3 CLASS 2" at 12434.48,4946.92 h60
  text "OTHER +/-" at 12434.46,4802.73 h60
  text "BOW & TWIST:" at 11408.23,4657.54 h60
  text "X" at 12256.46,4657.54 h60
  text "ANSI IPC-6012 TYPE 3 CLASS 2" at 12434.48,4657.54 h60
  text "OTHER +/-" at 12434.46,4510.85 h60
  text "DRILLING:" at 11333.46,4380.23 h60
  text "NC_DRILL FILES" at 13094.46,4275.04 h60
  text "REFERENCE:" at 11408.23,4271.1 h60
  text "X" at 12065.46,4271.01 h60
  text "AS SHOWN" at 12243.46,4271.1 h60
  text "X" at 12966.46,4271.1 h60
  text "OTHER" at 13392.46,4128.85 h60
  text "PTH COPPER THICKNESS:" at 11407.91,4125.32 h60
  text "X" at 12547.14,4125.32 h60
  text "20-30 um" at 12675.14,4125.32 h60
  text "BOARD FINISH:" at 11333.46,3977.73 h60
  text "SILKSCREEN:" at 11488.68,3867.6 h60
  text "X" at 12446.46,3867.6 h60
  text "TOP" at 12563.46,3867.6 h60
  text "X" at 12956.46,3867.6 h60
  text "BOTTOM" at 13074.46,3867.6 h60
  text "SILKSCREEN COLOR:" at 11488.68,3712.41 h60
  text "X" at 12445.46,3712.41 h60
  text "WHITE" at 12563.46,3712.41 h60
  text "OTHER" at 13074.46,3712.41 h60
  text "X" at 12576.46,3568.96 h60
  text "GREEN" at 12694.46,3568.96 h60
  text "OTHER" at 13312.46,3568.96 h60
  text "SOLDER RESIST COLOR:" at 11488.68,3562.1 h60
  text "X" at 12576.46,3414.71 h60
  text "MATTE" at 12694.46,3414.71 h60
  text "SEMI-GLOSS" at 13312,3414.07 h60
  text "IMMERSION GOLD (ENIG)" at 12394.46,3241.94 h60
  text "ENEPIG" at 13732,3234.72 h60
  text "SURFACE FINISH:" at 11333.46,3233.72 h60
  text "X" at 12216.46,3233.72 h60
  text "IMM. TIN/SILVER OR EQUIV" at 11663,3096.4 h60
  text "OTHER" at 13094.46,3092.47 h60
  text "ARRAY/PANEL:" at 11333.46,2937.09 h60
  text "CUT AND TRIM PER M1 BOARD OUTLINE" at 12394.46,2928.87 h60
  text "N.C. ROUTE" at 12394.46,2792.9 h60
  text "X" at 13082.46,2792.9 h60
  text "V. SCORE" at 13260.46,2792.9 h60
  text "CERTIFICATION:" at 11333.46,2663.77 h60
  text "MATERIALS AND WORKMANSHIP FOR ALL PCBS" at 12058.46,2663.77 h60
  text "TO MEET OR EXCEED THE REQUIREMENTS OF:" at 12058.46,2569.71 h60
  text "X" at 11695.97,2441.08 h60
  text "ANSI IPC-A-600F CLASS ->" at 11823.96,2441.08 h60
  text "X" at 13471.97,2441.08 h60
  text "2" at 13581.96,2441.08 h60
  text "1" at 13266.96,2439.58 h60
  text "3" at 13935.96,2439.58 h60
  text "X" at 12507.97,2293.39 h60
  text "RoHS" at 12635.96,2293.39 h60
  text "OTHER" at 13280.36,2293.39 h60
  text "PER ORDER" at 13677.42,2293.39 h60
  text "ALL BOARDS MUST MEET OR EXCEED UL94-V0 REQUIREMENTS." at 11361,2139.57 h60
  text "PCB MUST BEAR THE UL94V-0 UL REGISTERED MATERIAL ID NUMBER" at 11361,2023.5 h60
  text "ADDITIONAL REQUIREMENTS:" at 11333.46,1854.08 h60
  text "MICROSECTION:" at 11408.23,1746.95 h60
  text "YES" at 12313.96,1746.95 h60
  text "REQUIRED" at 13175.46,1602.62 h60
  text "BARE BOARD ELEC. TEST:" at 11408.23,1599.76 h60
  text "NONE" at 12713.96,1599.76 h60
  text "X" at 13057.46,1599.76 h60
  text "PER ORDER" at 13767.46,1599.76 h60
  text "XX MIL VIAS REQUIRE NON-CONDUCTIVE FILL AND PLANARIZE" at 11576.38,1394.82 h59
  text "XX MIL VIAS REQUIRE CONDUCTIVE FILL AND PLANARIZE" at 11584.38,1290.84 h60
  text "OUTER XX MIL TRACES REQUIRE 50 OHM SINGLE-ENDED IMPEDANCE" at 11583.39,1127.46 h58
  text "LAYER 2 & 3 (INNER LAYERS) XX MIL WIDE, XX MIL SPACE / TRACES REQUIRE 100 OHM DIFFERENTIAL IMPEDANCE" at 11575.39,891.74 h60
  text ".Layer_Name" at 577,-858.49 h60
M11 Gerber Information:
  lines w10: -292,-930.17 6308,-930.17 ; -292,-726.83 6310,-726.83 ; -292,-523.5 -292,-1133.5 3713,-1133.5 6310,-1133.5 6310,-523.5 -291.5,-523.5 -291.5,-1133.5 1284,-1133.5 ; 2173,-1133.5 2173,-523.5 ; 3440,-726.83 3440,-523.5 ; 4280,-726.83 4280,-523.5 ; 4902,-1140 4902,-937.17
  text "ALL ARTWORK VIEWED FROM TOP SIDE" at -228.5,-655.67 h60
  text "BOARD #:" at 2248,-655.67 h60
  text ".PRJ_Number" at 2793.5,-655.67 h60
  text "REV:" at 3638,-655.67 h60
  text ".PCB_Rev" at 3929.5,-655.67 h60
  text "SVN REV:" at 4476,-655.67 h60
  text ".VersionControl_RevNumber" at 4982,-655.67 h60
  text "LAYER NAME =" at -228.5,-858.49 h60
  text "TID #:" at 2248,-859 h60
  text ".TID" at 2793.5,-859 h60
  text "PLOT NAME =" at -228.5,-1064.34 h60
  text ".plot_File_Name" at 577,-1064.34 h60
  text "GENERATED    :" at 2250,-1064.34 h60
  text ".Print_Date" at 3119.5,-1064.34 h60
  text ".Print_Time" at 3848.5,-1064.34 h60
  text "TEXAS INSTRUMENTS" at 5113,-1064.34 h60
M12 Stackup:
  drawing of 399 lines, arcs and shapes, not listed
  text "Layer" at 6725.09,7755 h60
  text "Name" at 7135,7755 h60
  text "Material" at 8074.74,7755 h60
  text "Thickness" at 8934.51,7755 h60
  text "Constant" at 9584.34,7755 h60
  text "Board Layer Stack" at 10154.2,7755 h60
  text "Top Overlay" at 7135,7635 h60
  text "Top Solder" at 7135,7515 h60
  text "Solder Resist" at 8074.74,7515 h60
  text "0.40mil" at 8934.51,7515 h60
  text "3.5" at 9584.34,7515 h60
  text "1" at 6725.09,7395 h60
  text "Top Layer" at 7135,7395 h60
  text "2.80mil" at 8934.51,7395 h60
  text "Dielectric 2" at 7135,7275 h60
  text "7.00mil" at 8934.51,7275 h60
  text "4.2" at 9584.34,7275 h60
  text "2" at 6725.09,7155 h60
  text "Signal Layer 1" at 7135,7155 h60
  text "2.80mil" at 8934.51,7155 h60
  text "Dielectric 3" at 7135,7035 h60
  text "14.00mil" at 8934.51,7035 h60
  text "4.2" at 9584.34,7035 h60
  text "3" at 6725.09,6915 h60
  text "Signal Layer 2" at 7135,6915 h60
  text "2.80mil" at 8934.51,6915 h60
  text "Dielectric1" at 7135,6795 h60
  text "FR-4" at 8074.74,6795 h60
  text "7.00mil" at 8934.51,6795 h60
  text "4.2" at 9584.34,6795 h60
  text "4" at 6725.09,6675 h60
  text "Signal Layer 3" at 7135,6675 h60
  text "2.80mil" at 8934.51,6675 h60
  text "Dielectric 4" at 7135,6555 h60
  text "14.00mil" at 8934.51,6555 h60
  text "4.2" at 9584.34,6555 h60
  text "5" at 6725.09,6435 h60
  text "Signal Layer 4" at 7135,6435 h60
  text "2.80mil" at 8934.51,6435 h60
  text "Dielectric 5" at 7135,6315 h60
  text "7.00mil" at 8934.51,6315 h60
  text "4.2" at 9584.34,6315 h60
  text "6" at 6725.09,6195 h60
  text "Bottom Layer" at 7135,6195 h60
  text "2.80mil" at 8934.51,6195 h60
  text "Bottom Solder" at 7135,6075 h60
  text "Solder Resist" at 8074.74,6075 h60
  text "0.40mil" at 8934.51,6075 h60
  text "3.5" at 9584.34,6075 h60
  text "Bottom Overlay" at 7135,5955 h60
  text ".Layer_Name" at 577,-858.49 h60
M13 Component Bodies Top:
  text ".Layer_Name" at 577,-858.49 h60
M14 Component Bodies Bottom:
  text ".Layer_Name" at 577,-858.49 h60
M15 Courtyards Top:
  text ".Layer_Name" at 577,-858.49 h60
M16 Courtyards Bottom:
  text ".Layer_Name" at 577,-858.49 h60
Drill Drawing:
  text ".Layer_Name" at 577,-858.49 h60
M17 Embedded Cavity:
  text ".Layer_Name" at 577,-858.49 h60
M18 Embedded Assembly:
  text ".Layer_Name" at 577,-858.49 h60
M19 Embedded Keepout:
  text ".Layer_Name" at 577,-858.49 h60

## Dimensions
1902.73,3543.31 to 1902.73,2047.24 on Top Overlay
1902.73,2047 to 3795,2047.24 on Top Overlay
5918.48,866.14 to 5918.48,3543.31 on Top Overlay
1902.73,3543 to 5918.48,3543.31 on Top Overlay
0,-400 to 1000,-400 on M2 Board Dimensions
